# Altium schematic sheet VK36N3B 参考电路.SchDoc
size A4
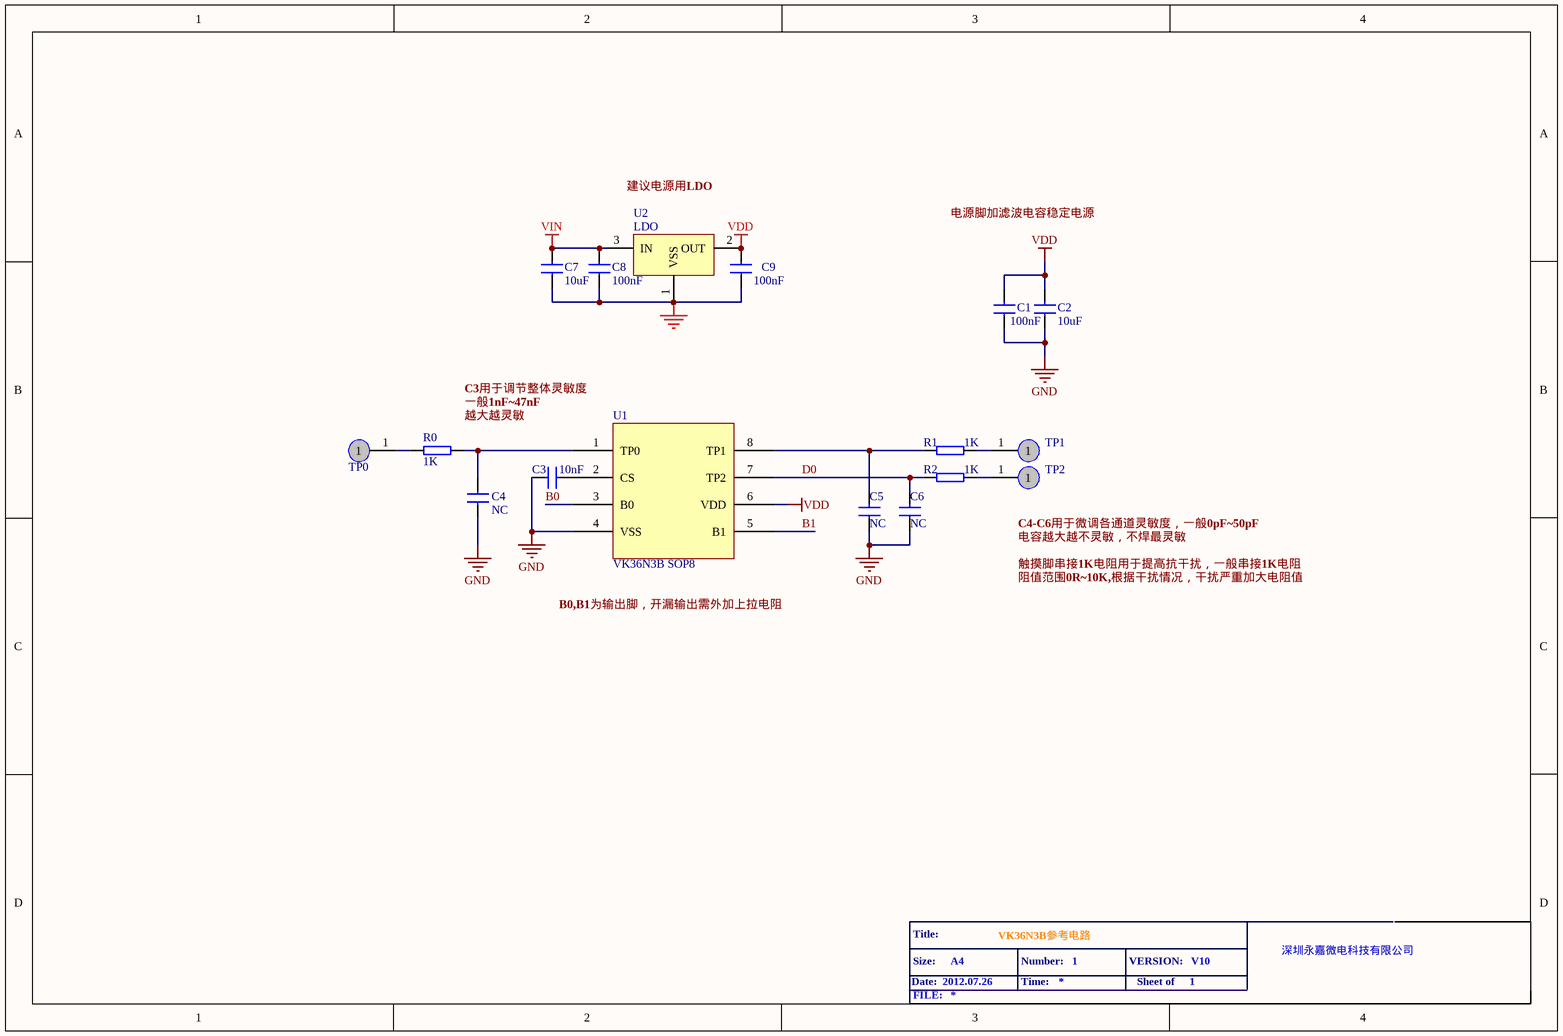
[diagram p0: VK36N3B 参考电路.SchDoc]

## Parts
C1  100nF  [0603-C]
C2  10uF  [0603-C]
C3  value 10nF  [0603-C]  (hidden comment: 10uF)
C4  value NC  [0603-C]  (hidden comment: 10uF)
C5  value NC  [0603-C]  (hidden comment: 10uF)
C6  value NC  [0603-C]  (hidden comment: 10uF)
C7  10uF  [0805-C]
C8  100nF  [0805-C]
C9  100nF  [0805-C]
R0  1K  [0603-R]
R1  1K  [0603-R]
R2  1K  [0603-R]
TP0  TPAD  [TP-PAD0]  (value not drawn)
TP1  TPAD  [TP-PAD0]  (value not drawn)
TP2  TPAD  [TP-PAD0]  (value not drawn)
U1  VK36N3B SOP8
U2  LDO  [SOT-23]

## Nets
GND: C1.2 C2.2 C3.2 C4.1 C5.1 C6.1 C7.2 C8.2 C9.2 U1.4(VSS) U2.1(VSS)
VDD: C1.1 C2.1 C9.1 U1.6(VDD) U2.2(OUT)
VIN: C7.1 C8.1 U2.3(IN)
B0: U1.3(B0)
B1: U1.5(B1)
D0: C6.2 R2.2 U1.7(TP2)
NetC3_1: C3.1 U1.2(CS)
NetC4_2: C4.2 R0.2 U1.1(TP0)
NetC5_2: C5.2 R1.2 U1.8(TP1)
NetR0_1: R0.1 TP0.1
NetR1_1: R1.1 TP1.1
NetR2_1: R2.1 TP2.1

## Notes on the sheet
- 建议电源用LDO
- 电源脚加滤波电容稳定电源
- C3用于调节整体灵敏度
- (near R0) 一般1nF~47nF
- (near R0) 越大越灵敏
- 触摸脚串接1K电阻用于提高抗干扰，一般串接1K电阻
- 阻值范围0R
  0K,根据干扰情况，干扰严重加大电阻值
- (near TP2) C4-C6用于微调各通道灵敏度，一般0pF~50pF
- 电容越大越不灵敏，不焊最灵敏
- B0,B1为输出脚，开漏输出需外加上拉电阻
- Date:
- Title:
- Size:
- 2012.07.26
- A4
- VK36N3B参考电路
- Number:
- Time:
- 1
- VERSION:
- Sheet of
- V10
- 深圳永嘉微电科技有限公司
- FILE:

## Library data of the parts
C1-C9 = CAP: Capacitor
R0-R2 = RES: Resistor
TP0-TP2 = TPAD: TESTING
U2 = V6206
